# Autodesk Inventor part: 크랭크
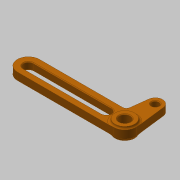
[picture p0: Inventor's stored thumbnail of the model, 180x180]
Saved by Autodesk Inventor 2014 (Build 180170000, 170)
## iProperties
Created: 2019-09
Part Number: 크랭크
Material: 알루미늄 6061
Document SubType Name: Modeling
Designer: mduedu
Density: 1 g/cm^3
Appearance: 주황색
Author: mduedu
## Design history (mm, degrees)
sketch "스케치1"
  geometry: L1 (0, 0)-(79, 0); L2 (0, 9)-(79, 9); L3 (10.637, -9)-(79, -9); L4 (0, 0)-(0, -25); L5 (-8.935, -1.08)-(-5.957, -25.72); L6 (7.659, -11.64)-(5.957, -25.72); L7 (79, -4)-(15, -4); L8 (15, 4)-(79, 4); C1 r 3 at (0, -25); A1 r 9 centre (0, 0) between (0, 9) and (-8.935, -1.08); A2 r 9 centre (79, 0) between (79, -9) and (79, 9); A3 r 6 centre (0, -25) between (-5.957, -25.72) and (5.957, -25.72); A4 r 3 centre (10.637, -12) between (10.637, -9) and (7.659, -11.64); A5 r 4 centre (79, 0) between (79, -4) and (79, 4); A6 r 4 centre (15, 0) between (15, -4) and (15, 4); 1 further point
  constraints: 16 end point, 13 point on circle, 12 tangent, 7 centre point, 5 coincident, 3 horizontal, 2 point on line, 1 equal radius, 1 perpendicular, 1 other
  dimensions: "d0" = 79 distance of L1.start L1.end; "d2" = 25 distance of L1.start L4.end; "d3" = 3 radius of A4; "d4" = 9 radius of A1; "d5" = 6 radius of A3; "d6" = 8 diameter of A5; "d7" = 64 distance of A6.centre L1.end; "d8" = 6 diameter of C1
extrude "돌출1" new body sketch "스케치1" stored distance "d9" = 6; taper "d10" = 0 deg
sketch "스케치2"
  geometry: C1 r 8 at (0, 0); 1 further point
  constraints: 1 centre point, 1 coincident
  dimensions: "d11" = 16 diameter of C1
extrude "돌출2" join sketch "스케치2" stored distance "d12" = 10; taper "d13" = 0 deg
sketch "스케치3"
  geometry: C1 r 4.5 at (0, 0); 1 further point
  constraints: 1 centre point, 1 coincident
  dimensions: "d14" = 9 diameter of C1
extrude "돌출3" cut sketch "스케치3" stored distance "d15" = 10; taper "d16" = 0 deg
fillet "모깎기1" dims "d17" = 2
chamfer "모따기1" distance "d18" = 0.5; stored, may be unused: second distance "d19" = 2, angle "d20" = 45 deg
node "솔리드1"
